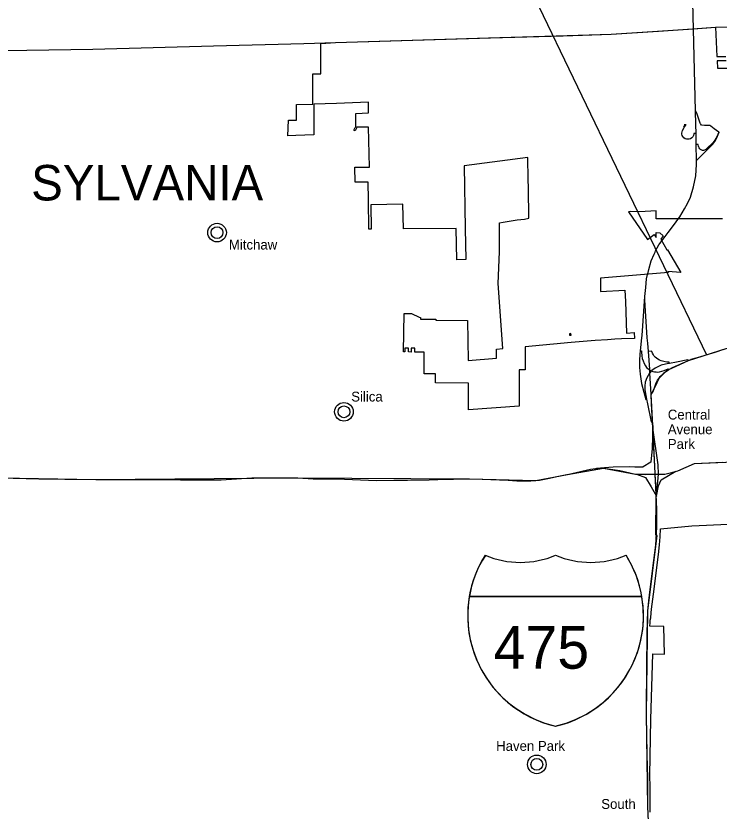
# Model space of a CAD drawing. Extents: x 0 to 750, y 0 to 507.
# Drawn here: x 180.7 to 255.1, y 253.1 to 337.1 of the extents above; entities that cross this region are included whole.
import ezdxf

# ---------------------------------------------------------------- set-up
doc = ezdxf.new("R2010")
doc.units = 0
for name, color, linetype in [('DV_X_Corp_Line', 7, 'Continuous'), ('GM_P_US_Alignment', 7, 'Continuous'), ('GM_X_Corporation_Text', 7, 'Continuous'), ('GM_X_County', 7, 'Continuous'), ('GM_X_Interchange_Ramps', 7, 'Continuous'), ('GM_X_Interstate_Route', 7, 'Continuous'), ('GM_X_State_Route', 7, 'Continuous'), ('GM_X_US_Route', 7, 'Continuous'), ('SH_Data', 7, 'Continuous')]:
    doc.layers.add(name, color=color, linetype=linetype)

msp = doc.modelspace()

# ---------------------------------------------------------------- linework, layer by layer
at = {"layer": 'DV_X_Corp_Line'}
for points in [[(255.407, 315.662), (248.414, 315.659), (248.413, 316.507), (246.672, 316.409), (245.733, 316.426), (245.476, 316.415), (247.479, 313.485), (248.189, 314.021), (248.398, 313.685), (248.401, 313.85), (248.407, 314.209), (248.797, 314.18), (249.143, 313.856), (248.893, 313.519), (249.543, 312.374), (249.6, 312.377), (251.023, 310.009), (249.641, 310.11), (249.712, 309.992), (242.51, 309.391), (242.511, 307.98), (245.088, 308.127), (245.149, 306.944), (245.272, 303.602), (246.091, 303.641), (246.104, 303.039), (244.729, 302.972), (244.03, 302.936), (243.252, 302.894), (241.969, 302.826), (239.435, 302.615), (234.555, 302.132), (234.551, 300.89), (234.547, 299.717), (233.932, 299.719), (233.928, 295.857), (228.566, 295.468), (228.572, 298.316), (225.092, 298.324), (225.092, 298.38), (225.092, 298.436), (225.091, 299.28), (223.871, 299.295), (223.868, 301.578), (222.885, 301.59), (222.89, 301.99), (222.501, 301.995), (222.496, 301.595), (222.214, 301.599), (222.219, 301.999), (222.031, 302.001), (221.844, 302.004), (221.839, 301.604), (221.714, 301.605), (221.766, 305.674), (222.546, 305.665), (223.346, 305.26), (223.496, 305.258), (223.495, 305.168), (223.494, 305.078), (225.107, 305.073), (225.106, 304.943), (228.461, 304.934), (228.516, 300.696), (231.543, 300.93), (231.544, 301.9), (232.196, 301.953), (231.699, 308.845), (231.826, 312.172), (231.827, 315.237), (232.232, 315.296), (233.719, 315.553), (234.48, 315.634), (234.931, 315.722), (234.892, 318.945), (234.866, 319.815), (234.838, 322.135), (228.099, 321.28), (228.215, 314.659), (228.273, 311.36), (227.318, 311.343), (227.26, 314.65), (221.713, 314.595), (221.643, 317.23), (218.247, 317.157), (218.293, 314.59), (218.045, 314.59), (218.015, 317.681), (217.955, 319.54), (216.579, 319.54), (216.542, 321.123), (218.088, 321.136), (218.014, 325.364), (216.782, 325.343), (216.744, 325.292), (216.713, 325.242), (216.688, 325.192), (216.588, 324.968), (216.452, 325.032), (216.552, 325.255), (216.573, 325.299), (216.61, 325.358), (216.646, 325.406), (216.646, 326.806), (218.009, 326.877), (217.989, 328.003), (214.601, 327.838), (212.22, 327.797), (212.233, 324.539), (210.316, 324.465), (209.486, 324.436), (209.544, 326.077), (210.371, 326.106), (210.371, 327.76), (212.128, 327.791), (212.128, 330.982), (212.952, 330.996), (212.952, 334.204), (214.509, 334.284), (230.671, 334.776), (237.848, 334.994), (243.649, 335.171), (248.664, 335.502), (252.233, 335.746), (254.675, 335.932), (254.822, 332.811), (255.778, 332.811)], [(255.786, 332.361), (254.844, 332.361), (254.881, 331.572), (256.475, 331.573)], [(247.768, 252.975), (247.752, 254.307), (247.776, 255.613), (247.74, 256.901), (247.832, 262.778), (248.057, 269.704), (249.278, 269.686), (249.198, 272.579), (247.723, 272.643), (247.776, 272.988), (247.776, 273.253), (247.835, 273.499), (247.871, 274.048), (247.92, 274.43), (248.123, 276.003), (248.635, 280.191), (248.754, 281.211), (248.813, 282.068), (248.855, 282.899), (252.184, 283.225), (253.725, 283.293), (255.984, 283.421)]]:
    msp.add_lwpolyline(points, dxfattribs=at)
msp.add_lwpolyline([(239.229, 303.531), (239.236, 303.365), (239.401, 303.374), (239.394, 303.54)], close=True, dxfattribs=at)
for centre, radius in [((201.992, 314.213), 0.982), ((201.992, 314.213), 0.623), ((215.4, 295.28), 0.982), ((215.4, 295.28), 0.623), ((235.785, 258.025), 0.982), ((235.785, 258.025), 0.623)]:
    msp.add_circle(centre, radius, dxfattribs=at)
at = {"layer": 'GM_P_US_Alignment'}
for points in [[(249.219, 236.614), (248.814, 240.716), (248.102, 247.343), (247.632, 251.233), (247.516, 253.545), (247.395, 263.332), (247.521, 274.256), (248.511, 282.211), (248.511, 282.211), (248.382, 282.254), (248.418, 286.54), (248.262, 289.495), (248.064, 293.827), (247.886, 297.091), (248.325, 298.001), (248.704, 298.832), (249.492, 299.601), (250.125, 299.961), (251.804, 300.69), (255.795, 301.978), (256.69, 302.166), (257.425, 302.18), (263.283, 302.22)], [(121.925, 287.941), (132.365, 287.845), (149.553, 287.753), (162.9, 288.301), (179.1, 288.291), (189.18, 288.131), (210.045, 288.307), (228.664, 288.186), (235.692, 288.005), (239.037, 288.663), (242.838, 289.339), (246.214, 288.691), (249.312, 288.691), (250.676, 289.038), (252.444, 289.82), (262.398, 290.25), (262.452, 289.379), (262.694, 289.121), (264.953, 287.17), (265.312, 286.649), (265.728, 285.606), (265.832, 284.123), (265.822, 283.582)]]:
    msp.add_lwpolyline(points, dxfattribs=at)
at = {"layer": 'GM_X_Corporation_Text'}
for p, q in [((228.65, 275.747), (246.894, 275.747)), ((246.894, 275.747), (228.65, 275.747)), ((246.894, 275.747), (228.65, 275.747))]:
    msp.add_line(p, q, dxfattribs=at)
for centre, radius, start, end in [((240.471, 273.737), 11.99, 147.82161, 256.99413), ((239.721, 273.945), 11.216, 146.65397, 170.75899), ((234.048, 288.935), 9.567, 247.08482, 292.91053), ((234.048, 288.935), 9.567, 247.08482, 292.91053), ((235.074, 273.737), 11.989, 283.00654, 32.17868), ((241.497, 288.937), 9.569, 247.09162, 292.90836), ((241.497, 288.937), 9.569, 247.09162, 292.90836), ((235.074, 273.737), 11.99, 9.64753, 32.17902), ((240.47, 273.737), 11.989, 170.35136, 256.9967), ((235.098, 273.733), 11.966, 282.76665, 9.68983)]:
    msp.add_arc(centre, radius, start, end, dxfattribs=at)
at = {"layer": 'GM_X_County'}
msp.add_lwpolyline([(174.879, 333.37), (188.864, 333.599), (201.627, 333.931), (211.161, 334.182), (214.509, 334.284), (230.891, 334.782), (238.555, 335.016), (243.643, 335.171), (252.35, 335.754), (254.675, 335.934), (262.292, 336.044), (263.849, 336.065), (266.19, 336.123), (274.975, 336.21), (278.568, 336.396), (281.798, 336.467), (285.861, 336.545), (293.537, 336.782), (296.285, 336.866), (300.489, 337.079), (303.777, 337.225)], dxfattribs=at)
at = {"layer": 'GM_X_Interchange_Ramps'}
for points in [[(252.614, 324.679), (252.395, 324.676), (252.392, 324.653), (252.353, 324.479), (252.263, 324.317), (252.156, 324.211), (252.037, 324.13), (251.892, 324.078), (251.755, 324.072), (251.602, 324.076), (251.452, 324.13), (251.326, 324.222), (251.219, 324.349), (251.163, 324.469), (251.127, 324.6), (251.121, 324.732), (251.146, 324.87), (251.197, 324.994), (251.366, 325.328), (251.389, 325.374), (251.423, 325.424), (251.423, 325.425), (251.482, 325.476), (251.553, 325.53), (251.552, 325.668)], [(251.366, 325.328), (251.326, 325.348), (251.421, 325.525), (251.422, 325.67)], [(255.037, 324.837), (254.98, 324.757), (254.832, 324.416), (254.696, 324.152), (254.616, 323.993), (254.508, 323.833), (254.379, 323.695), (253.768, 323.08), (253.65, 322.987), (253.511, 322.924), (253.394, 322.903), (253.286, 322.901), (253.173, 322.949), (253.079, 323.003), (253.005, 323.065), (252.943, 323.157), (252.899, 323.247), (252.861, 323.352), (252.835, 323.479), (252.831, 323.536), (252.633, 323.533)], [(247.221, 307.464), (247.177, 307.464), (246.882, 303.33), (246.857, 303.076), (246.726, 301.723), (246.691, 301.367), (246.656, 300.707), (246.656, 299.943), (246.709, 299.248), (246.865, 298.258), (247.108, 297.355), (247.299, 296.573), (247.394, 296.596)], [(246.726, 301.723), (246.838, 301.721), (246.847, 301.562), (246.879, 301.191), (246.934, 300.921), (247.019, 300.655), (247.136, 300.378), (247.263, 300.14), (247.39, 299.97), (247.519, 299.844), (247.683, 299.712), (247.728, 299.689), (247.863, 299.619), (247.915, 299.598), (248.053, 299.545), (248.219, 299.503), (248.386, 299.483), (248.564, 299.477), (248.761, 299.5), (248.987, 299.557), (249.23, 299.634), (249.673, 299.806), (249.724, 299.746)], [(249.823, 300.395), (249.769, 300.516), (249.512, 300.538), (249.215, 300.585), (248.946, 300.665), (248.755, 300.736), (248.586, 300.825), (248.435, 300.927), (248.304, 301.044), (248.193, 301.171), (248.11, 301.298), (248.018, 301.461), (247.949, 301.645), (247.94, 301.679), (247.581, 301.652)], [(251.804, 300.69), (251.764, 300.766), (250.546, 300.516), (249.823, 300.395), (249.712, 300.377), (248.931, 300.203), (248.289, 299.891), (247.959, 299.647), (247.915, 299.598), (247.745, 299.405), (247.698, 299.352), (247.42, 298.866), (247.247, 298.397), (247.195, 297.98), (247.195, 297.598), (247.394, 296.596), (247.491, 296.109), (247.868, 294.211), (248.019, 294.231)]]:
    msp.add_lwpolyline(points, dxfattribs=at)
at = {"layer": 'GM_X_Interstate_Route'}
for points in [[(254.508, 301.539), (254.53, 301.545), (254.733, 301.597), (255.452, 301.843), (255.574, 301.891)], [(249.166, 299.34), (249.192, 299.366), (249.724, 299.746), (250.903, 300.292), (251.804, 300.69), (252.063, 300.805)], [(252.063, 300.805), (252.106, 300.823), (252.629, 300.982), (253.012, 301.096)], [(253.012, 301.096), (254.508, 301.539)], [(247.886, 297.091), (248.069, 297.426), (248.208, 297.81), (248.39, 298.35), (248.545, 298.621), (248.704, 298.832), (248.828, 299.002), (249.166, 299.34)], [(248.262, 289.495), (248.262, 289.495), (248.019, 294.231), (247.921, 296.144), (247.886, 297.091)], [(248.286, 288.726), (248.262, 289.495)], [(247.521, 274.256), (247.616, 275.311), (247.743, 276.229), (248.154, 279.577), (248.349, 281.174), (248.462, 283.099), (248.481, 284.989), (248.418, 286.54), (248.39, 287.241), (248.299, 288.526)], [(248.299, 288.526), (248.288, 288.669), (248.286, 288.697), (248.286, 288.71), (248.286, 288.726)], [(247.393, 264.053), (247.448, 271.931), (247.521, 274.256)], [(248.927, 239.631), (248.814, 240.716), (248.608, 242.559), (248.515, 243.398), (248.102, 247.343), (247.855, 249.311), (247.851, 249.343), (247.718, 250.487), (247.632, 251.233), (247.516, 253.545), (247.526, 254.828), (247.504, 255.943), (247.509, 256.824), (247.498, 257.56), (247.431, 261), (247.395, 263.332), (247.393, 264.053)]]:
    msp.add_lwpolyline(points, dxfattribs=at)
at = {"layer": 'GM_X_State_Route'}
for points in [[(253.128, 325.656), (253.08, 325.712), (253.036, 325.762), (252.858, 326.286), (252.715, 326.813), (252.554, 327.094)], [(254.18, 325.466), (254.082, 325.54), (253.523, 325.536), (253.203, 325.57), (253.128, 325.656)], [(255.068, 324.815), (255.037, 324.837), (254.542, 325.189), (254.18, 325.466)], [(252.661, 321.839), (253.253, 322.442), (253.881, 323.071), (254.341, 323.517), (254.59, 323.846), (254.779, 324.154), (255.068, 324.815)]]:
    msp.add_lwpolyline(points, dxfattribs=at)
at = {"layer": 'GM_X_US_Route'}
for p, q in [((252.444, 289.82), (255.439, 289.97)), ((248.427, 286.326), (248.647, 288.676))]:
    msp.add_line(p, q, dxfattribs=at)
for points in [[(252.554, 327.094), (252.283, 338.572)], [(252.593, 325.618), (252.592, 325.644), (252.554, 327.094)], [(252.656, 322.093), (252.656, 322.101), (252.638, 323.237), (252.633, 323.533), (252.614, 324.679), (252.593, 325.618)], [(250.874, 315.826), (250.897, 315.856), (250.916, 315.89), (251.397, 316.732), (251.719, 317.27), (252.038, 317.958), (252.356, 319.048), (252.581, 320.203), (252.661, 321.415), (252.661, 321.839), (252.656, 322.093)], [(248.282, 312.153), (248.345, 312.293), (248.696, 312.932), (248.796, 313.062), (249.138, 313.509), (249.667, 314.22), (250.333, 315.115), (250.874, 315.826)], [(247.5, 309.8), (247.512, 309.854), (247.609, 310.297), (247.889, 311.233), (248.189, 311.946), (248.282, 312.153)], [(247.509, 302.524), (247.461, 303.105), (247.252, 306.526), (247.219, 307.093), (247.221, 307.464), (247.316, 308.41), (247.397, 309.332), (247.5, 309.8)], [(247.886, 297.091), (247.745, 299.405), (247.728, 299.689), (247.723, 299.766), (247.581, 301.652), (247.509, 302.524)], [(248.064, 293.827), (247.971, 291.398), (247.832, 289.941), (247.023, 289.455)], [(248.647, 288.674), (248.615, 289.685), (248.055, 293.6)], [(238.955, 288.646), (239.037, 288.663), (241.449, 289.216), (241.989, 289.292)], [(241.989, 289.292), (242.838, 289.339), (244.549, 289.062), (246.214, 288.691), (247.254, 288.645), (249.312, 288.691), (250.676, 289.038), (252.444, 289.82)], [(242.08, 289.305), (242.08, 289.305), (242.947, 289.403), (243.87, 289.452), (245.632, 289.507), (246.147, 289.445), (246.58, 289.455), (246.715, 289.458), (246.773, 289.46), (247.032, 289.466)], [(162.9, 288.301), (169.083, 288.362), (173.603, 288.355), (175.618, 288.349), (179.1, 288.291), (183.17, 288.186), (185.895, 288.162), (189.18, 288.131), (198.123, 288.084), (202.422, 288.085)], [(202.422, 288.085), (205.656, 288.301)], [(205.656, 288.301), (205.656, 288.301), (210.045, 288.307), (210.521, 288.29), (212.137, 288.193), (212.928, 288.193), (213.82, 288.182), (213.945, 288.179)], [(215.445, 288.148), (218.85, 288.036), (220.673, 288.046), (222.126, 288.049), (224.427, 288.104), (225.329, 288.112), (228.664, 288.186), (230.025, 288.149), (232.763, 288.055), (233.689, 287.993), (234.674, 287.968), (235.161, 287.975), (235.692, 288.005), (236.085, 288.071), (237.124, 288.271), (237.911, 288.433), (238.955, 288.646)], [(246.333, 288.686), (247.277, 288.344), (247.873, 287.363), (248.425, 286.366)], [(248.425, 286.366), (248.647, 287.452), (248.92, 288.089), (250.488, 288.991)], [(213.945, 288.179), (215.445, 288.148)]]:
    msp.add_lwpolyline(points, dxfattribs=at)
at = {"layer": 'SH_Data'}
msp.add_line((233.602, 343.091), (253.719, 301.308), dxfattribs=at)

# ---------------------------------------------------------------- texts
at = {"layer": 'DV_X_Corp_Line'}
for s, p in [('Mitchaw', (203.244, 312.418)), ('Silica', (216.171, 296.364)), ('Central', (249.632, 294.46)), ('Avenue', (249.632, 292.91)), ('Park', (249.632, 291.36)), ('Haven Park', (231.489, 259.455)), ('South', (242.599, 253.322))]:
    msp.add_text(s, height=1.0417, rotation=0.00001, dxfattribs=at).set_placement(p)
at = {"layer": 'GM_X_Corporation_Text'}
msp.add_text('SYLVANIA', height=3.7501, rotation=0.00001, dxfattribs=at).set_placement((182.344, 317.607))
msp.add_text('475', height=4.5281, dxfattribs=at).set_placement((231.218, 268.132))

doc.saveas('drawing.dxf')
